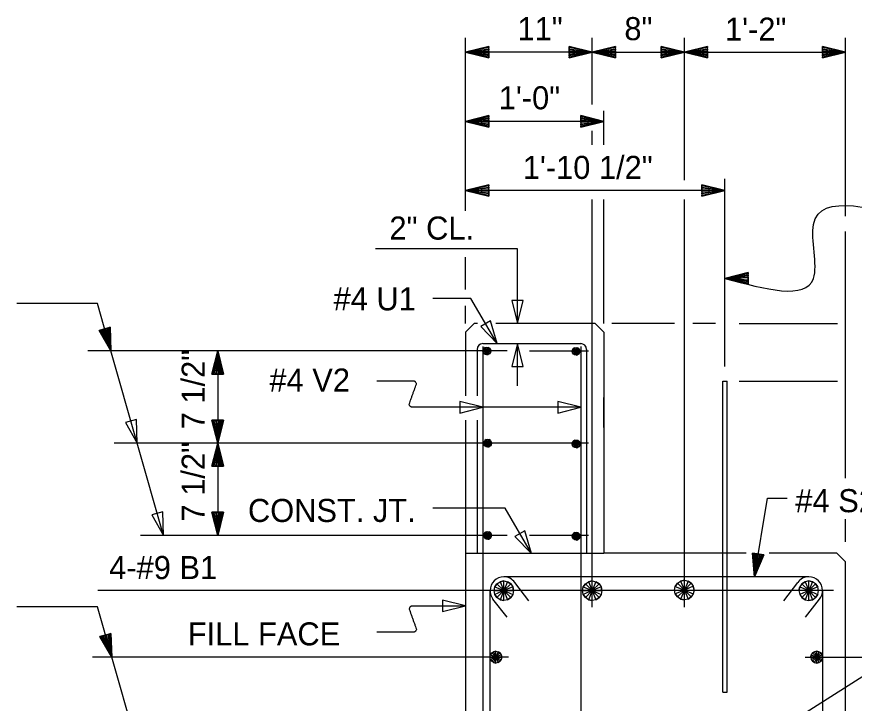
# Model space of a CAD drawing. Extents: x -41 to 191, y -168 to 6.
# Drawn here: x 40.67 to 51.05, y -152.58 to -144.08 of the extents above; entities that cross this region are included whole.
import ezdxf

# ---------------------------------------------------------------- set-up
doc = ezdxf.new("R2010")
doc.units = 0
for name, color, linetype in [('Arrowhead Terminators CELL', 7, 'Continuous'), ('Default', 7, 'Continuous'), ('Dimension Lines', 7, 'Continuous'), ('Dimension Lines CELL', 7, 'Continuous'), ('Rebar Lines', 7, 'Continuous'), ('Rebar Lines CELL', 7, 'Continuous'), ('sub interior bent cap lines', 7, 'Continuous'), ('Text', 7, 'Continuous'), ('Text CELL', 7, 'Continuous')]:
    doc.layers.add(name, color=color, linetype=linetype)

msp = doc.modelspace()

# ---------------------------------------------------------------- linework, layer by layer
at = {"layer": 'Arrowhead Terminators CELL'}
for points in [[(46.521, -144.519), (46.521, -144.533), (46.234, -144.519), (46.521, -144.547), (46.521, -144.562), (46.234, -144.519), (46.521, -144.576), (46.521, -144.59), (46.234, -144.519), (46.521, -144.447), (46.521, -144.462), (46.234, -144.519), (46.521, -144.476), (46.521, -144.49), (46.234, -144.519), (46.521, -144.504), (46.521, -144.59), (46.521, -144.447), (46.234, -144.519), (46.521, -144.59)], [(47.518, -144.519), (47.518, -144.504), (47.804, -144.519), (47.518, -144.49), (47.518, -144.476), (47.804, -144.519), (47.518, -144.462), (47.518, -144.447), (47.804, -144.519), (47.518, -144.59), (47.518, -144.576), (47.804, -144.519), (47.518, -144.562), (47.518, -144.547), (47.804, -144.519), (47.518, -144.533), (47.518, -144.447), (47.518, -144.59), (47.804, -144.519), (47.518, -144.447)], [(48.09, -144.519), (48.09, -144.533), (47.804, -144.519), (48.09, -144.547), (48.09, -144.562), (47.804, -144.519), (48.09, -144.576), (48.09, -144.59), (47.804, -144.519), (48.09, -144.447), (48.09, -144.462), (47.804, -144.519), (48.09, -144.476), (48.09, -144.49), (47.804, -144.519), (48.09, -144.504), (48.09, -144.59), (48.09, -144.447), (47.804, -144.519), (48.09, -144.59)], [(48.659, -144.519), (48.659, -144.504), (48.945, -144.519), (48.659, -144.49), (48.659, -144.476), (48.945, -144.519), (48.659, -144.462), (48.659, -144.447), (48.945, -144.519), (48.659, -144.59), (48.659, -144.576), (48.945, -144.519), (48.659, -144.562), (48.659, -144.547), (48.945, -144.519), (48.659, -144.533), (48.659, -144.447), (48.659, -144.59), (48.945, -144.519), (48.659, -144.447)], [(49.231, -144.519), (49.231, -144.533), (48.945, -144.519), (49.231, -144.547), (49.231, -144.562), (48.945, -144.519), (49.231, -144.576), (49.231, -144.59), (48.945, -144.519), (49.231, -144.447), (49.231, -144.462), (48.945, -144.519), (49.231, -144.476), (49.231, -144.49), (48.945, -144.519), (49.231, -144.504), (49.231, -144.59), (49.231, -144.447), (48.945, -144.519), (49.231, -144.59)], [(50.657, -144.519), (50.657, -144.504), (50.943, -144.519), (50.657, -144.49), (50.657, -144.476), (50.943, -144.519), (50.657, -144.462), (50.657, -144.447), (50.943, -144.519), (50.657, -144.59), (50.657, -144.576), (50.943, -144.519), (50.657, -144.562), (50.657, -144.547), (50.943, -144.519), (50.657, -144.533), (50.657, -144.447), (50.657, -144.59), (50.943, -144.519), (50.657, -144.447)], [(46.521, -145.375), (46.521, -145.389), (46.234, -145.375), (46.521, -145.404), (46.521, -145.418), (46.234, -145.375), (46.521, -145.432), (46.521, -145.446), (46.234, -145.375), (46.521, -145.303), (46.521, -145.318), (46.234, -145.375), (46.521, -145.332), (46.521, -145.346), (46.234, -145.375), (46.521, -145.361), (46.521, -145.446), (46.521, -145.303), (46.234, -145.375), (46.521, -145.446)], [(47.661, -145.375), (47.661, -145.361), (47.947, -145.375), (47.661, -145.346), (47.661, -145.332), (47.947, -145.375), (47.661, -145.318), (47.661, -145.303), (47.947, -145.375), (47.661, -145.446), (47.661, -145.432), (47.947, -145.375), (47.661, -145.418), (47.661, -145.404), (47.947, -145.375), (47.661, -145.389), (47.661, -145.303), (47.661, -145.446), (47.947, -145.375), (47.661, -145.303)], [(46.521, -146.231), (46.521, -146.245), (46.234, -146.231), (46.521, -146.26), (46.521, -146.274), (46.234, -146.231), (46.521, -146.288), (46.521, -146.303), (46.234, -146.231), (46.521, -146.16), (46.521, -146.174), (46.234, -146.231), (46.521, -146.188), (46.521, -146.202), (46.234, -146.231), (46.521, -146.217), (46.521, -146.303), (46.521, -146.16), (46.234, -146.231), (46.521, -146.303)], [(49.162, -146.231), (49.162, -146.217), (49.448, -146.231), (49.162, -146.202), (49.162, -146.188), (49.448, -146.231), (49.162, -146.174), (49.162, -146.16), (49.448, -146.231), (49.162, -146.303), (49.162, -146.288), (49.448, -146.231), (49.162, -146.274), (49.162, -146.26), (49.448, -146.231), (49.162, -146.245), (49.162, -146.16), (49.162, -146.303), (49.448, -146.231), (49.162, -146.16)], [(49.734, -147.319), (49.734, -147.333), (49.448, -147.319), (49.734, -147.347), (49.734, -147.362), (49.448, -147.319), (49.734, -147.376), (49.734, -147.39), (49.448, -147.319), (49.734, -147.247), (49.734, -147.261), (49.448, -147.319), (49.734, -147.276), (49.734, -147.29), (49.448, -147.319), (49.734, -147.304), (49.734, -147.39), (49.734, -147.247), (49.448, -147.319), (49.734, -147.39)], [(41.764, -147.944), (41.75, -147.948), (41.842, -148.218), (41.736, -147.952), (41.723, -147.956), (41.842, -148.218), (41.709, -147.96), (41.695, -147.964), (41.842, -148.218), (41.832, -147.925), (41.818, -147.929), (41.842, -148.218), (41.805, -147.932), (41.791, -147.936), (41.842, -148.218), (41.777, -147.94), (41.695, -147.964), (41.832, -147.925), (41.842, -148.218), (41.695, -147.964)], [(43.164, -148.504), (43.15, -148.504), (43.164, -148.218), (43.136, -148.504), (43.121, -148.504), (43.164, -148.218), (43.107, -148.504), (43.093, -148.504), (43.164, -148.218), (43.236, -148.504), (43.221, -148.504), (43.164, -148.218), (43.207, -148.504), (43.193, -148.504), (43.164, -148.218), (43.178, -148.504), (43.093, -148.504), (43.236, -148.504), (43.164, -148.218), (43.093, -148.504)], [(43.164, -149.073), (43.178, -149.073), (43.164, -149.359), (43.193, -149.073), (43.207, -149.073), (43.164, -149.359), (43.221, -149.073), (43.236, -149.073), (43.164, -149.359), (43.093, -149.073), (43.107, -149.073), (43.164, -149.359), (43.121, -149.073), (43.136, -149.073), (43.164, -149.359), (43.15, -149.073), (43.236, -149.073), (43.093, -149.073), (43.164, -149.359), (43.236, -149.073)], [(43.164, -149.645), (43.15, -149.645), (43.164, -149.359), (43.136, -149.645), (43.121, -149.645), (43.164, -149.359), (43.107, -149.645), (43.093, -149.645), (43.164, -149.359), (43.236, -149.645), (43.221, -149.645), (43.164, -149.359), (43.207, -149.645), (43.193, -149.645), (43.164, -149.359), (43.178, -149.645), (43.093, -149.645), (43.236, -149.645), (43.164, -149.359), (43.093, -149.645)], [(43.164, -150.215), (43.178, -150.215), (43.164, -150.501), (43.193, -150.215), (43.207, -150.215), (43.164, -150.501), (43.221, -150.215), (43.236, -150.215), (43.164, -150.501), (43.093, -150.215), (43.107, -150.215), (43.164, -150.501), (43.121, -150.215), (43.136, -150.215), (43.164, -150.501), (43.15, -150.215), (43.236, -150.215), (43.093, -150.215), (43.164, -150.501), (43.236, -150.215)], [(49.861, -150.732), (49.875, -150.734), (49.814, -151.014), (49.889, -150.736), (49.903, -150.739), (49.814, -151.014), (49.917, -150.741), (49.931, -150.743), (49.814, -151.014), (49.79, -150.72), (49.804, -150.722), (49.814, -151.014), (49.818, -150.725), (49.832, -150.727), (49.814, -151.014), (49.846, -150.729), (49.931, -150.743), (49.79, -150.72), (49.814, -151.014), (49.931, -150.743)], [(41.773, -151.735), (41.76, -151.739), (41.851, -152.009), (41.746, -151.743), (41.732, -151.747), (41.851, -152.009), (41.719, -151.75), (41.705, -151.754), (41.851, -152.009), (41.842, -151.715), (41.828, -151.719), (41.851, -152.009), (41.814, -151.723), (41.801, -151.727), (41.851, -152.009), (41.787, -151.731), (41.705, -151.754), (41.842, -151.715), (41.851, -152.009), (41.705, -151.754)]]:
    msp.add_lwpolyline(points, dxfattribs=at)
for points in [[(46.877, -147.876), (46.948, -147.592), (46.806, -147.592)], [(46.628, -148.126), (46.545, -147.844), (46.423, -147.916)], [(46.877, -148.126), (46.806, -148.411), (46.948, -148.411)], [(46.448, -148.915), (46.164, -148.844), (46.164, -148.986)], [(47.661, -148.915), (47.377, -148.844), (47.377, -148.986)], [(42.167, -149.359), (42.158, -149.066), (42.021, -149.105)], [(42.493, -150.501), (42.483, -150.208), (42.346, -150.247)], [(47.05, -150.725), (46.968, -150.443), (46.845, -150.515)], [(46.234, -151.374), (45.95, -151.303), (45.95, -151.445)]]:
    msp.add_lwpolyline(points, close=True, dxfattribs=at)
at = {"layer": 'Default'}
msp.add_line((46.234, -150.723), (47.947, -150.723), dxfattribs=at)
at = {"layer": 'Dimension Lines'}
msp.add_line((49.448, -148.41), (49.448, -146.088), dxfattribs=at)
at = {"layer": 'Dimension Lines CELL'}
for p, q in [((46.234, -146.482), (46.234, -144.343)), ((47.804, -145.166), (47.804, -144.343)), ((48.945, -146.104), (48.945, -144.343)), ((50.943, -146.547), (50.943, -144.343)), ((47.804, -144.519), (46.234, -144.519)), ((47.804, -144.519), (48.945, -144.519)), ((48.945, -144.519), (50.943, -144.519)), ((47.947, -145.664), (47.947, -145.243)), ((47.947, -145.375), (46.234, -145.375)), ((47.804, -145.664), (47.804, -145.492)), ((49.445, -146.231), (46.234, -146.231)), ((47.804, -151.39), (47.804, -146.342)), ((47.947, -147.876), (47.947, -146.342)), ((48.945, -151.39), (48.945, -146.342)), ((50.943, -149.792), (50.943, -146.74)), ((46.877, -146.955), (45.118, -146.955)), ((46.877, -147.876), (46.877, -146.955)), ((46.234, -147.455), (46.234, -147.055)), ((46.234, -147.876), (46.234, -147.657)), ((48.824, -147.876), (48.047, -147.876)), ((49.332, -147.876), (49.052, -147.876)), ((49.625, -147.876), (50.843, -147.876)), ((46.877, -148.65), (46.877, -148.126)), ((46.752, -148.218), (41.556, -148.218)), ((43.164, -148.218), (43.164, -149.359)), ((47.759, -148.222), (47.025, -148.222)), ((49.625, -148.59), (50.843, -148.59)), ((47.949, -149.167), (47.949, -148.792)), ((47.661, -148.915), (46.234, -148.915)), ((47.759, -149.359), (41.882, -149.359)), ((43.164, -149.359), (43.164, -150.501)), ((50.943, -150.58), (50.943, -150.302)), ((46.752, -150.501), (42.207, -150.501)), ((47.759, -150.501), (47.025, -150.501)), ((50.793, -151.185), (41.678, -151.185)), ((46.767, -152.009), (41.612, -152.009)), ((50.443, -152.009), (51.304, -152.009))]:
    msp.add_line(p, q, dxfattribs=at)
for points in [[(41.842, -148.218), (41.674, -147.629), (40.674, -147.629)], [(46.628, -148.126), (46.301, -147.568), (45.829, -147.568)], [(42.167, -149.359), (41.842, -148.218)], [(42.493, -150.501), (42.167, -149.359)], [(49.814, -151.014), (49.974, -150.04), (50.219, -150.04)], [(47.05, -150.725), (46.724, -150.166), (45.829, -150.166)], [(49.21, -153.477), (52.782, -151.213), (53.331, -151.213)], [(41.851, -152.009), (41.674, -151.386), (40.674, -151.386)], [(42.137, -153.009), (41.851, -152.009)]]:
    msp.add_lwpolyline(points, dxfattribs=at)
msp.add_spline([(49.448, -147.319), (50.545, -147.319), (50.545, -146.651), (51.996, -146.651)], degree=3, dxfattribs=at)
for points in [[(46.234, -148.913), (46.017, -148.913), (45.799, -148.913), (45.581, -148.913), (45.577, -148.913), (45.573, -148.913), (45.569, -148.912), (45.565, -148.912), (45.562, -148.911), (45.559, -148.91), (45.553, -148.907), (45.548, -148.904), (45.546, -148.899), (45.538, -148.887), (45.536, -148.875), (45.541, -148.863), (45.554, -148.826), (45.567, -148.789), (45.581, -148.752), (45.594, -148.715), (45.608, -148.678), (45.621, -148.641), (45.626, -148.629), (45.624, -148.616), (45.616, -148.604), (45.613, -148.6), (45.609, -148.596), (45.603, -148.594), (45.6, -148.593), (45.597, -148.592), (45.593, -148.591), (45.589, -148.591), (45.585, -148.59), (45.581, -148.59), (45.432, -148.59), (45.284, -148.59), (45.135, -148.59)], [(46.234, -151.376), (46.017, -151.376), (45.799, -151.376), (45.581, -151.376), (45.577, -151.376), (45.573, -151.376), (45.569, -151.377), (45.565, -151.377), (45.562, -151.378), (45.559, -151.38), (45.553, -151.382), (45.548, -151.385), (45.546, -151.39), (45.538, -151.402), (45.536, -151.415), (45.541, -151.426), (45.554, -151.463), (45.567, -151.5), (45.581, -151.537), (45.594, -151.575), (45.608, -151.612), (45.621, -151.649), (45.626, -151.66), (45.624, -151.673), (45.616, -151.685), (45.613, -151.69), (45.609, -151.693), (45.603, -151.695), (45.6, -151.697), (45.597, -151.698), (45.593, -151.698), (45.589, -151.699), (45.585, -151.699), (45.581, -151.699), (45.432, -151.699), (45.284, -151.699), (45.135, -151.699)]]:
    msp.add_open_spline(points, degree=3, dxfattribs=at)
at = {"layer": 'Rebar Lines'}
for centre, start, end in [((46.448, -148.198), 90, 180), ((47.661, -148.198), 0, 90)]:
    msp.add_arc(centre, 0.0713, start, end, dxfattribs=at)
at = {"layer": 'Rebar Lines CELL'}
for p, q in [((46.448, -148.126), (47.661, -148.126)), ((46.377, -148.198), (46.377, -148.772)), ((46.448, -148.162), (46.448, -154.809)), ((47.661, -148.162), (47.661, -154.809)), ((47.733, -148.198), (47.733, -150.723)), ((49.421, -152.443), (49.421, -148.59)), ((49.421, -148.59), (49.475, -148.59)), ((49.475, -152.443), (49.475, -148.59)), ((46.377, -149.076), (46.377, -150.723)), ((50.486, -151.014), (46.708, -151.014)), ((47.018, -151.313), (46.846, -151.083)), ((50.176, -151.313), (50.349, -151.083)), ((46.537, -151.185), (46.537, -151.589)), ((50.657, -151.185), (50.657, -151.628)), ((46.749, -151.515), (46.574, -151.291)), ((50.445, -151.515), (50.621, -151.291)), ((46.537, -151.589), (46.537, -157.034)), ((50.657, -151.589), (50.657, -157.034)), ((49.421, -152.443), (49.475, -152.443))]:
    msp.add_line(p, q, dxfattribs=at)
for points in [[(46.498, -148.17), (46.516, -148.173), (46.532, -148.184), (46.543, -148.199), (46.546, -148.218), (46.543, -148.236), (46.532, -148.252), (46.516, -148.263), (46.498, -148.266), (46.479, -148.263), (46.464, -148.252), (46.453, -148.236), (46.45, -148.218), (46.453, -148.199), (46.464, -148.184), (46.479, -148.173), (46.498, -148.17), (46.498, -148.218), (46.498, -148.266), (46.516, -148.263), (46.498, -148.218), (46.532, -148.252), (46.543, -148.236), (46.498, -148.218), (46.546, -148.218), (46.543, -148.199), (46.498, -148.218), (46.532, -148.184), (46.516, -148.173), (46.498, -148.218), (46.479, -148.173), (46.464, -148.184), (46.498, -148.218), (46.453, -148.199), (46.45, -148.218), (46.498, -148.218), (46.453, -148.236), (46.464, -148.252), (46.498, -148.218), (46.479, -148.263)], [(47.604, -148.174), (47.622, -148.178), (47.638, -148.188), (47.648, -148.204), (47.652, -148.222), (47.648, -148.241), (47.638, -148.256), (47.622, -148.267), (47.604, -148.271), (47.585, -148.267), (47.57, -148.256), (47.559, -148.241), (47.555, -148.222), (47.559, -148.204), (47.569, -148.188), (47.585, -148.178), (47.604, -148.174), (47.604, -148.222), (47.604, -148.271), (47.622, -148.267), (47.604, -148.222), (47.638, -148.256), (47.648, -148.241), (47.604, -148.222), (47.652, -148.222), (47.648, -148.204), (47.604, -148.222), (47.638, -148.188), (47.622, -148.178), (47.604, -148.222), (47.585, -148.178), (47.569, -148.188), (47.604, -148.222), (47.559, -148.204), (47.555, -148.222), (47.604, -148.222), (47.559, -148.241), (47.57, -148.256), (47.604, -148.222), (47.585, -148.267)], [(46.509, -149.311), (46.527, -149.315), (46.543, -149.325), (46.553, -149.341), (46.557, -149.359), (46.553, -149.378), (46.543, -149.394), (46.527, -149.404), (46.509, -149.408), (46.49, -149.404), (46.475, -149.394), (46.464, -149.378), (46.46, -149.359), (46.464, -149.341), (46.474, -149.325), (46.49, -149.315), (46.509, -149.311), (46.509, -149.359), (46.509, -149.408), (46.527, -149.404), (46.509, -149.359), (46.543, -149.394), (46.553, -149.378), (46.509, -149.359), (46.557, -149.359), (46.553, -149.341), (46.509, -149.359), (46.543, -149.325), (46.527, -149.315), (46.509, -149.359), (46.49, -149.315), (46.474, -149.325), (46.509, -149.359), (46.464, -149.341), (46.46, -149.359), (46.509, -149.359), (46.464, -149.378), (46.475, -149.394), (46.509, -149.359), (46.49, -149.404)], [(47.605, -149.321), (47.624, -149.324), (47.639, -149.335), (47.65, -149.35), (47.654, -149.369), (47.65, -149.387), (47.639, -149.403), (47.624, -149.414), (47.605, -149.417), (47.587, -149.414), (47.571, -149.403), (47.561, -149.388), (47.557, -149.369), (47.561, -149.35), (47.571, -149.335), (47.587, -149.324), (47.605, -149.321), (47.605, -149.369), (47.605, -149.417), (47.624, -149.414), (47.605, -149.369), (47.639, -149.403), (47.65, -149.387), (47.605, -149.369), (47.654, -149.369), (47.65, -149.35), (47.605, -149.369), (47.639, -149.335), (47.624, -149.324), (47.605, -149.369), (47.587, -149.324), (47.571, -149.335), (47.605, -149.369), (47.561, -149.35), (47.557, -149.369), (47.605, -149.369), (47.561, -149.388), (47.571, -149.403), (47.605, -149.369), (47.587, -149.414)], [(46.509, -150.453), (46.527, -150.456), (46.543, -150.467), (46.553, -150.482), (46.557, -150.501), (46.553, -150.519), (46.543, -150.535), (46.527, -150.546), (46.509, -150.549), (46.49, -150.546), (46.475, -150.535), (46.464, -150.52), (46.46, -150.501), (46.464, -150.482), (46.474, -150.467), (46.49, -150.456), (46.509, -150.453), (46.509, -150.501), (46.509, -150.549), (46.527, -150.546), (46.509, -150.501), (46.543, -150.535), (46.553, -150.519), (46.509, -150.501), (46.557, -150.501), (46.553, -150.482), (46.509, -150.501), (46.543, -150.467), (46.527, -150.456), (46.509, -150.501), (46.49, -150.456), (46.474, -150.467), (46.509, -150.501), (46.464, -150.482), (46.46, -150.501), (46.509, -150.501), (46.464, -150.52), (46.475, -150.535), (46.509, -150.501), (46.49, -150.546)], [(47.605, -150.462), (47.624, -150.466), (47.639, -150.476), (47.65, -150.492), (47.654, -150.511), (47.65, -150.529), (47.639, -150.545), (47.624, -150.555), (47.605, -150.559), (47.587, -150.555), (47.571, -150.545), (47.561, -150.529), (47.557, -150.511), (47.561, -150.492), (47.571, -150.476), (47.587, -150.466), (47.605, -150.462), (47.605, -150.511), (47.605, -150.559), (47.624, -150.555), (47.605, -150.511), (47.639, -150.545), (47.65, -150.529), (47.605, -150.511), (47.654, -150.511), (47.65, -150.492), (47.605, -150.511), (47.639, -150.476), (47.624, -150.466), (47.605, -150.511), (47.587, -150.466), (47.571, -150.476), (47.605, -150.511), (47.561, -150.492), (47.557, -150.511), (47.605, -150.511), (47.561, -150.529), (47.571, -150.545), (47.605, -150.511), (47.587, -150.555)], [(48.824, -151.178), (48.833, -151.132), (48.859, -151.092), (48.899, -151.066), (48.945, -151.057), (48.991, -151.066), (49.03, -151.092), (49.056, -151.131), (49.065, -151.178), (49.056, -151.224), (49.03, -151.263), (48.991, -151.289), (48.945, -151.298), (48.899, -151.289), (48.86, -151.263), (48.833, -151.224), (48.824, -151.178), (48.945, -151.178), (49.065, -151.178), (49.056, -151.131), (48.945, -151.178), (49.03, -151.092), (48.991, -151.066), (48.945, -151.178), (48.945, -151.057), (48.899, -151.066), (48.945, -151.178), (48.859, -151.092), (48.833, -151.132), (48.945, -151.178), (48.833, -151.224), (48.86, -151.263), (48.945, -151.178), (48.899, -151.289), (48.945, -151.298), (48.945, -151.178), (48.991, -151.289), (49.03, -151.263), (48.945, -151.178), (49.056, -151.224)], [(46.588, -151.185), (46.597, -151.139), (46.623, -151.1), (46.662, -151.074), (46.708, -151.065), (46.755, -151.074), (46.794, -151.1), (46.82, -151.139), (46.829, -151.185), (46.82, -151.231), (46.794, -151.27), (46.755, -151.297), (46.708, -151.306), (46.662, -151.297), (46.623, -151.271), (46.597, -151.232), (46.588, -151.185), (46.708, -151.185), (46.829, -151.185), (46.82, -151.139), (46.708, -151.185), (46.794, -151.1), (46.755, -151.074), (46.708, -151.185), (46.708, -151.065), (46.662, -151.074), (46.708, -151.185), (46.623, -151.1), (46.597, -151.139), (46.708, -151.185), (46.597, -151.232), (46.623, -151.271), (46.708, -151.185), (46.662, -151.297), (46.708, -151.306), (46.708, -151.185), (46.755, -151.297), (46.794, -151.27), (46.708, -151.185), (46.82, -151.231)], [(47.683, -151.185), (47.693, -151.139), (47.719, -151.1), (47.758, -151.074), (47.804, -151.065), (47.85, -151.074), (47.889, -151.1), (47.915, -151.139), (47.924, -151.185), (47.915, -151.231), (47.889, -151.27), (47.85, -151.297), (47.804, -151.306), (47.758, -151.297), (47.719, -151.271), (47.693, -151.232), (47.683, -151.185), (47.804, -151.185), (47.924, -151.185), (47.915, -151.139), (47.804, -151.185), (47.889, -151.1), (47.85, -151.074), (47.804, -151.185), (47.804, -151.065), (47.758, -151.074), (47.804, -151.185), (47.719, -151.1), (47.693, -151.139), (47.804, -151.185), (47.693, -151.232), (47.719, -151.271), (47.804, -151.185), (47.758, -151.297), (47.804, -151.306), (47.804, -151.185), (47.85, -151.297), (47.889, -151.27), (47.804, -151.185), (47.915, -151.231)], [(50.606, -151.185), (50.597, -151.139), (50.571, -151.1), (50.532, -151.074), (50.486, -151.065), (50.44, -151.074), (50.401, -151.1), (50.375, -151.139), (50.365, -151.185), (50.375, -151.231), (50.401, -151.27), (50.44, -151.297), (50.486, -151.306), (50.532, -151.297), (50.571, -151.271), (50.597, -151.232), (50.606, -151.185), (50.486, -151.185), (50.365, -151.185), (50.375, -151.139), (50.486, -151.185), (50.401, -151.1), (50.44, -151.074), (50.486, -151.185), (50.486, -151.065), (50.532, -151.074), (50.486, -151.185), (50.571, -151.1), (50.597, -151.139), (50.486, -151.185), (50.597, -151.232), (50.571, -151.271), (50.486, -151.185), (50.532, -151.297), (50.486, -151.306), (50.486, -151.185), (50.44, -151.297), (50.401, -151.27), (50.486, -151.185), (50.375, -151.231)], [(46.537, -152.009), (46.543, -151.981), (46.558, -151.957), (46.582, -151.942), (46.61, -151.936), (46.637, -151.942), (46.661, -151.957), (46.676, -151.981), (46.682, -152.009), (46.676, -152.036), (46.661, -152.06), (46.637, -152.076), (46.61, -152.081), (46.582, -152.076), (46.558, -152.06), (46.543, -152.036), (46.537, -152.009), (46.61, -152.009), (46.682, -152.009), (46.676, -151.981), (46.61, -152.009), (46.661, -151.957), (46.637, -151.942), (46.61, -152.009), (46.61, -151.936), (46.582, -151.942), (46.61, -152.009), (46.558, -151.957), (46.543, -151.981), (46.61, -152.009), (46.543, -152.036), (46.558, -152.06), (46.61, -152.009), (46.582, -152.076), (46.61, -152.081), (46.61, -152.009), (46.637, -152.076), (46.661, -152.06), (46.61, -152.009), (46.676, -152.036)], [(50.657, -152.009), (50.652, -151.981), (50.636, -151.957), (50.612, -151.942), (50.585, -151.936), (50.557, -151.942), (50.534, -151.957), (50.518, -151.981), (50.512, -152.009), (50.518, -152.036), (50.534, -152.06), (50.557, -152.076), (50.585, -152.081), (50.612, -152.076), (50.636, -152.06), (50.652, -152.036), (50.657, -152.009), (50.585, -152.009), (50.512, -152.009), (50.518, -151.981), (50.585, -152.009), (50.534, -151.957), (50.557, -151.942), (50.585, -152.009), (50.585, -151.936), (50.612, -151.942), (50.585, -152.009), (50.636, -151.957), (50.652, -151.981), (50.585, -152.009), (50.652, -152.036), (50.636, -152.06), (50.585, -152.009), (50.612, -152.076), (50.585, -152.081), (50.585, -152.009), (50.557, -152.076), (50.534, -152.06), (50.585, -152.009), (50.518, -152.036)]]:
    msp.add_lwpolyline(points, dxfattribs=at)
for centre, start, end in [((46.709, -151.185), 90, 180), ((46.708, -151.185), 36.8281, 90), ((50.486, -151.185), 90, 143.1719), ((50.486, -151.185), 0, 90), ((46.709, -151.185), 180, 218.0399), ((50.486, -151.185), 321.9601, 0)]:
    msp.add_arc(centre, 0.171, start, end, dxfattribs=at)
at = {"layer": 'sub interior bent cap lines'}
for p, q in [((46.234, -147.983), (46.341, -147.876)), ((46.384, -147.876), (46.341, -147.876)), ((47.84, -147.876), (46.609, -147.876)), ((47.947, -147.983), (47.84, -147.876)), ((49.709, -150.723), (47.947, -150.723)), ((50.835, -150.723), (49.997, -150.723)), ((50.943, -150.83), (50.835, -150.723)), ((50.943, -157.143), (50.943, -150.83))]:
    msp.add_line(p, q, dxfattribs=at)
for points in [[(46.234, -147.983), (46.234, -148.772)], [(47.947, -147.983), (47.947, -150.723)], [(46.234, -149.076), (46.234, -155.149)]]:
    msp.add_lwpolyline(points, dxfattribs=at)

# ---------------------------------------------------------------- texts
at = {"layer": 'Text'}
msp.add_text('FILL FACE', height=0.2854, dxfattribs=at).set_placement((42.794, -151.863))
at = {"layer": 'Text CELL'}
for s, height, p in [('11"', 0.2854, (46.878, -144.37)), ('8"', 0.2854, (48.202, -144.37)), ('1\'-2"', 0.2854, (49.449, -144.376)), ('1\'-0"', 0.2854, (46.646, -145.226)), ('1\'-10 1/2"', 0.2854, (46.944, -146.088)), ('2" CL.', 0.2859, (45.291, -146.839)), ('#4 U1', 0.2859, (44.599, -147.715)), ('#4 V2', 0.2859, (43.804, -148.721)), ('#4 S2', 0.2859, (50.32, -150.214)), ('CONST. JT.', 0.2854, (43.539, -150.335)), ('4-#9 B1', 0.2859, (41.819, -151.042))]:
    msp.add_text(s, height=height, dxfattribs=at).set_placement(p)
for p in [(43.003, -149.188), (43.003, -150.329)]:
    msp.add_text('7 1/2"', height=0.2854, rotation=90, dxfattribs=at).set_placement(p)

doc.saveas('drawing.dxf')
